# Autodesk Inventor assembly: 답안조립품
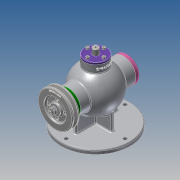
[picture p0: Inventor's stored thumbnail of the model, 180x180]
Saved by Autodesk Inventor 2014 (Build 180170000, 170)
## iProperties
Created: 2020-08
Part Number: 답안조립품
Document SubType Name: Assembly
Designer: kb542
Author: kb542
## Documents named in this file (18)
- C:\Users\kb542\Desktop\700806V1041\답안조립품.iam
- C:\Users\kb542\Desktop\700806V1041\본체.ipt
- C:\Users\kb542\Desktop\700806V1041\V-벨트풀리.ipt
- C:\Users\kb542\Desktop\700806V1041\너트 M8.ipt
- C:\Users\kb542\Desktop\700806V1041\뒤커버.ipt
- C:\Users\kb542\Desktop\700806V1041\멈춤링 15x1.ipt
- C:\Users\kb542\Desktop\700806V1041\멈춤링 35x1.6.ipt
- 멈춤링 35x1.6.ipt
- C:\Users\kb542\Desktop\700806V1041\베어링 6202.ipt
- 베어링 6202.ipt
- C:\Users\kb542\Desktop\700806V1041\볼트 M4.ipt
- C:\Users\kb542\Desktop\700806V1041\상부커버.ipt
- C:\Users\kb542\Desktop\700806V1041\슬라이드.ipt
- C:\Users\kb542\Desktop\700806V1041\앞커버.ipt
- C:\Users\kb542\Desktop\700806V1041\오일 실 15 30 7.ipt
- C:\Users\kb542\Desktop\700806V1041\칼라.ipt
- C:\Users\kb542\Desktop\700806V1041\키 3x3x12.ipt
- C:\Users\kb542\Desktop\700806V1041\편심축.ipt
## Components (1 placed, 1 different names)
1. V-벨트풀리:1
